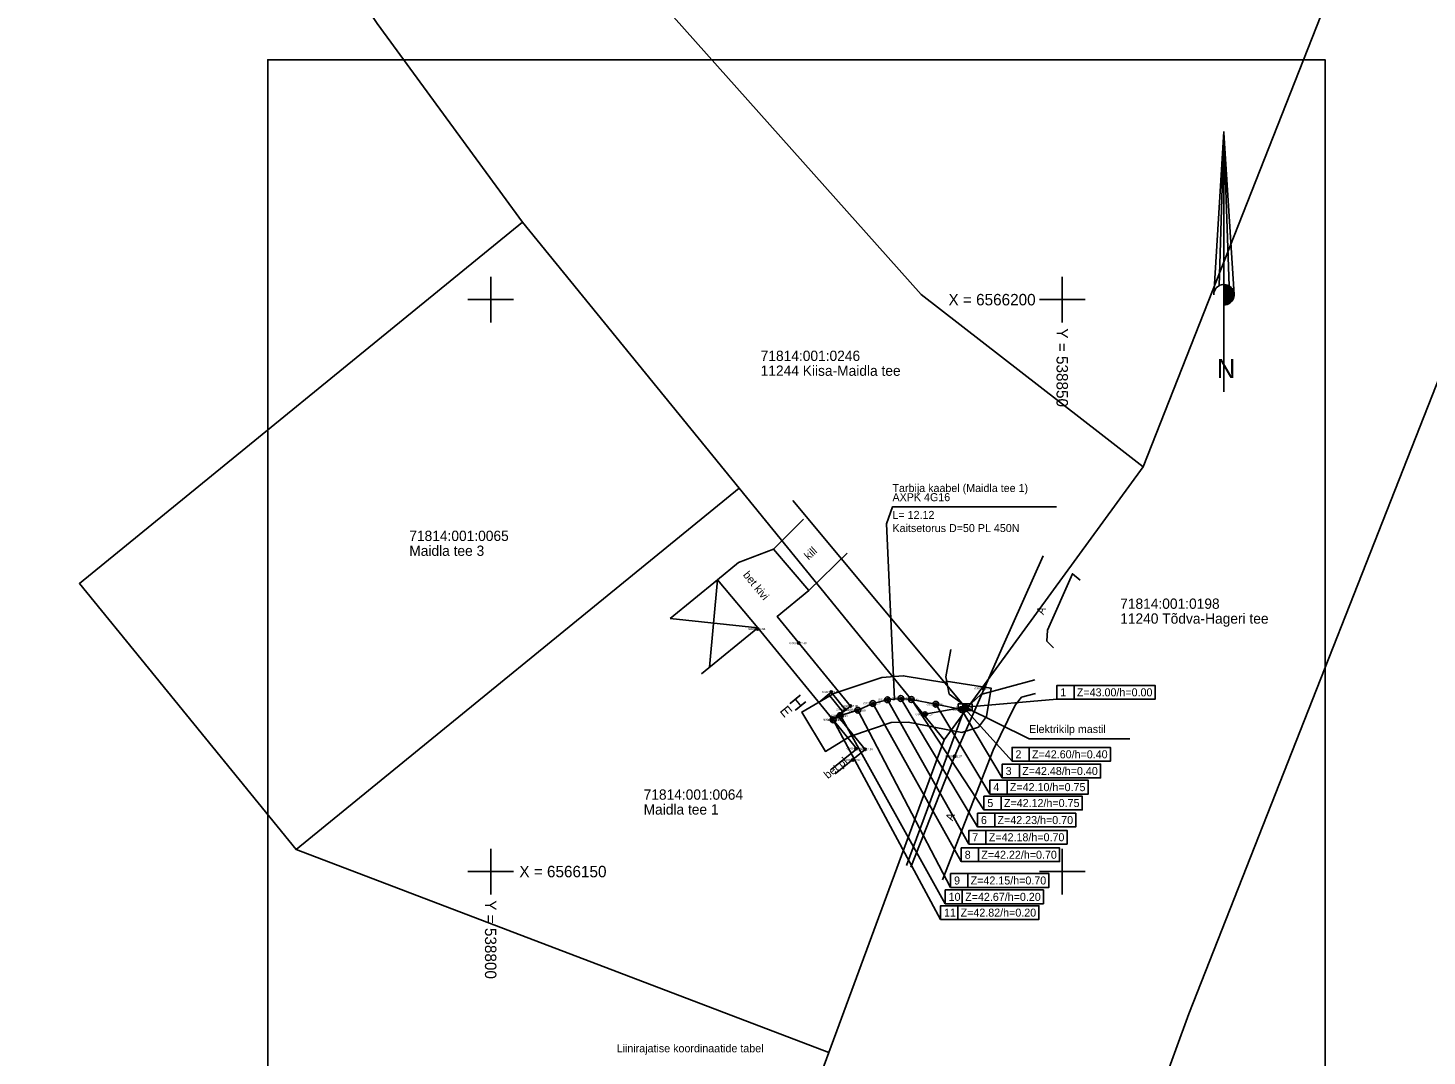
# Model space of a CAD drawing. Extents: x 537202 to 539193, y 6564585 to 6568304.
# Drawn here: x 538759.5 to 538881.9, y 6566133.9 to 6566223.7 of the extents above; entities that cross this region are included whole.
import ezdxf

# ---------------------------------------------------------------- set-up
doc = ezdxf.new("R2010")
doc.units = 0
for name, color, linetype in [('ABIJOONIS', 7, 'Continuous'), ('ELRAJATISMP', 7, 'Continuous'), ('HOONE', 7, 'Continuous'), ('HOONEDET', 7, 'Continuous'), ('KOORDPUNKT', 7, 'Continuous'), ('MOOTKORG-EH2000', 7, 'Continuous'), ('MOOTMPUNKT', 7, 'Continuous'), ('MOOTNR', 7, 'Continuous'), ('MOOTPIIR', 7, 'Continuous'), ('MPKAABEL', 7, 'Continuous'), ('MPOHULIIN', 7, 'Continuous'), ('PIIR', 7, 'Continuous'), ('POST', 7, 'Continuous'), ('TEE', 7, 'Continuous'), ('VORK', 7, 'Continuous'), ('VORMISTUS', 7, 'Continuous')]:
    doc.layers.add(name, color=color, linetype=linetype)

msp = doc.modelspace()

# ---------------------------------------------------------------- linework, layer by layer
at = {"layer": 'ABIJOONIS'}
for p, q in [((538851.03, 6566165.07), (538851.03, 6566166.27)), ((538847.11, 6566159.65), (538847.11, 6566160.85)), ((538846.25, 6566158.19), (538846.25, 6566159.39)), ((538845.17, 6566156.78), (538845.17, 6566157.98)), ((538844.65, 6566155.39), (538844.65, 6566156.59)), ((538844.09, 6566153.9), (538844.09, 6566155.1)), ((538843.33, 6566152.4), (538843.33, 6566153.6)), ((538842.67, 6566150.87), (538842.67, 6566152.07)), ((538841.74, 6566148.62), (538841.74, 6566149.82)), ((538841.26, 6566147.19), (538841.26, 6566148.39)), ((538840.86, 6566145.81), (538840.86, 6566147.01))]:
    msp.add_line(p, q, dxfattribs=at)
for points in [[(538841.51, 6566164.36), (538849.53, 6566165.07), (538858.13, 6566165.07), (538858.13, 6566166.27), (538849.53, 6566166.27), (538849.53, 6566165.07)], [(538833.43, 6566164.69), (538841.17, 6566150.87), (538849.77, 6566150.87), (538849.77, 6566152.07), (538841.17, 6566152.07), (538841.17, 6566150.87)], [(538834.71, 6566165.02), (538841.83, 6566152.4), (538850.43, 6566152.4), (538850.43, 6566153.6), (538841.83, 6566153.6), (538841.83, 6566152.4)], [(538835.89, 6566165.13), (538842.59, 6566153.9), (538851.19, 6566153.9), (538851.19, 6566155.1), (538842.59, 6566155.1), (538842.59, 6566153.9)], [(538836.8, 6566165.04), (538843.15, 6566155.39), (538851.75, 6566155.39), (538851.75, 6566156.59), (538843.15, 6566156.59), (538843.15, 6566155.39)], [(538838.95, 6566164.63), (538843.67, 6566156.78), (538852.27, 6566156.78), (538852.27, 6566157.98), (538843.67, 6566157.98), (538843.67, 6566156.78)], [(538830.59, 6566163.64), (538839.76, 6566147.19), (538848.36, 6566147.19), (538848.36, 6566148.39), (538839.76, 6566148.39), (538839.76, 6566147.19)], [(538832.12, 6566164.1), (538840.24, 6566148.62), (538848.84, 6566148.62), (538848.84, 6566149.82), (538840.24, 6566149.82), (538840.24, 6566148.62)], [(538841.2, 6566164.16), (538844.75, 6566158.19), (538853.35, 6566158.19), (538853.35, 6566159.39), (538844.75, 6566159.39), (538844.75, 6566158.19)], [(538841.49, 6566164.23), (538845.61, 6566159.65), (538854.21, 6566159.65), (538854.21, 6566160.85), (538845.61, 6566160.85), (538845.61, 6566159.65)], [(538829.96, 6566163.26), (538839.36, 6566145.81), (538847.96, 6566145.81), (538847.96, 6566147.01), (538839.36, 6566147.01), (538839.36, 6566145.81)]]:
    msp.add_lwpolyline(points, dxfattribs=at)
at = {"layer": 'ELRAJATISMP'}
for p, q in [((538841.37, 6566164.66), (538841.37, 6566164.07)), ((538841.64, 6566164.66), (538841.64, 6566164.07))]:
    msp.add_line(p, q, dxfattribs=at)
msp.add_lwpolyline([(538840.91, 6566164.66), (538842.11, 6566164.66), (538842.11, 6566164.07), (538840.91, 6566164.07)], close=True, dxfattribs=at)
msp.add_lwpolyline([(538841.51, 6566164.36), (538847.1, 6566161.61), (538855.92, 6566161.61)], dxfattribs=at)
at = {"layer": 'HOONE'}
msp.add_line((538830.79, 6566163.98), (538829.56, 6566165.5), dxfattribs=at)
for points in [[(538815.69, 6566172.11), (538819.84, 6566175.49), (538823.38, 6566171.3)], [(538829.8, 6566158.93), (538832.03, 6566160.73), (538823.38, 6566171.3), (538818.45, 6566167.29)], [(538828.7, 6566164.79), (538829.79, 6566165.69), (538831.02, 6566164.17), (538829.94, 6566163.28)]]:
    msp.add_lwpolyline(points, dxfattribs=at)
at = {"layer": 'HOONEDET'}
for p, q in [((538819.84, 6566175.49), (538819.15, 6566167.86)), ((538823.38, 6566171.3), (538815.69, 6566172.11)), ((538830.38, 6566163.59), (538832.76, 6566160.68))]:
    msp.add_line(p, q, dxfattribs=at)
at = {"layer": 'KOORDPUNKT'}
for centre, radius in [((538833.43, 6566164.69), 0.25), ((538833.43, 6566164.69), 0.0221), ((538833.43, 6566164.69), 0.025), ((538833.43, 6566164.69), 0.0132), ((538833.43, 6566164.69), 0.0161), ((538833.43, 6566164.69), 0.0191), ((538833.43, 6566164.69), 0.0043), ((538833.43, 6566164.69), 0.00726), ((538833.43, 6566164.69), 0.0102), ((538834.71, 6566165.02), 0.25), ((538834.71, 6566165.02), 0.025), ((538834.71, 6566165.02), 0.0221), ((538834.71, 6566165.02), 0.0161), ((538834.71, 6566165.02), 0.0191), ((538834.71, 6566165.02), 0.0102), ((538834.71, 6566165.02), 0.0132), ((538834.71, 6566165.02), 0.0043), ((538834.71, 6566165.02), 0.00726), ((538835.89, 6566165.13), 0.25), ((538835.89, 6566165.13), 0.025), ((538835.89, 6566165.13), 0.0221), ((538835.89, 6566165.13), 0.0132), ((538835.89, 6566165.13), 0.0161), ((538835.89, 6566165.13), 0.0191), ((538835.89, 6566165.13), 0.0043), ((538835.89, 6566165.13), 0.00726), ((538835.89, 6566165.13), 0.0102), ((538836.8, 6566165.04), 0.25), ((538836.8, 6566165.04), 0.0221), ((538836.8, 6566165.04), 0.025), ((538836.8, 6566165.04), 0.0161), ((538836.8, 6566165.04), 0.0191), ((538836.8, 6566165.04), 0.0132), ((538836.8, 6566165.04), 0.00726), ((538836.8, 6566165.04), 0.0102), ((538836.8, 6566165.04), 0.0043), ((538838.95, 6566164.63), 0.25), ((538838.95, 6566164.63), 0.025), ((538838.95, 6566164.63), 0.0221), ((538838.95, 6566164.63), 0.0161), ((538838.95, 6566164.63), 0.0191), ((538838.95, 6566164.63), 0.0102), ((538838.95, 6566164.63), 0.0132), ((538838.95, 6566164.63), 0.0043), ((538838.95, 6566164.63), 0.00726), ((538829.96, 6566163.26), 0.25), ((538830.59, 6566163.64), 0.25), ((538830.59, 6566163.64), 0.0191), ((538830.59, 6566163.64), 0.0221), ((538830.59, 6566163.64), 0.025), ((538830.59, 6566163.64), 0.0161), ((538830.59, 6566163.64), 0.0102), ((538830.59, 6566163.64), 0.0132), ((538830.59, 6566163.64), 0.00726), ((538830.59, 6566163.64), 0.0043), ((538832.12, 6566164.1), 0.25), ((538832.12, 6566164.1), 0.0221), ((538832.12, 6566164.1), 0.025), ((538832.12, 6566164.1), 0.0191), ((538832.12, 6566164.1), 0.0132), ((538832.12, 6566164.1), 0.0161), ((538832.12, 6566164.1), 0.0102), ((538832.12, 6566164.1), 0.0043), ((538832.12, 6566164.1), 0.00726), ((538841.2, 6566164.16), 0.25), ((538841.2, 6566164.16), 0.025), ((538841.2, 6566164.16), 0.0191), ((538841.2, 6566164.16), 0.0221), ((538841.2, 6566164.16), 0.0132), ((538841.2, 6566164.16), 0.0161), ((538841.2, 6566164.16), 0.0102), ((538841.2, 6566164.16), 0.0043), ((538841.2, 6566164.16), 0.00726), ((538841.49, 6566164.23), 0.25), ((538841.51, 6566164.36), 0.188), ((538841.49, 6566164.23), 0.025), ((538841.49, 6566164.23), 0.0221), ((538841.49, 6566164.23), 0.0161), ((538841.49, 6566164.23), 0.0191), ((538841.49, 6566164.23), 0.0102), ((538841.49, 6566164.23), 0.0132), ((538841.51, 6566164.36), 0.0143), ((538841.51, 6566164.36), 0.0165), ((538841.51, 6566164.36), 0.0188), ((538841.49, 6566164.23), 0.0043), ((538841.49, 6566164.23), 0.00726), ((538841.51, 6566164.36), 0.0121), ((538841.51, 6566164.36), 0.00323), ((538841.51, 6566164.36), 0.00545), ((538841.51, 6566164.36), 0.00766), ((538841.51, 6566164.36), 0.00988), ((538829.96, 6566163.26), 0.0221), ((538829.96, 6566163.26), 0.025), ((538829.96, 6566163.26), 0.0191), ((538829.96, 6566163.26), 0.0102), ((538829.96, 6566163.26), 0.0132), ((538829.96, 6566163.26), 0.0161), ((538829.96, 6566163.26), 0.0043), ((538829.96, 6566163.26), 0.00726)]:
    msp.add_circle(centre, radius, dxfattribs=at)
at = {"layer": 'MOOTMPUNKT'}
for centre in [(538823.35, 6566171.2), (538826.95, 6566169.97), (538843.12, 6566166), (538829.79, 6566165.69), (538833.43, 6566164.69), (538834.71, 6566165.02), (538835.89, 6566165.13), (538836.8, 6566165.04), (538838.95, 6566164.63), (538830.38, 6566163.59), (538830.59, 6566163.64), (538831.02, 6566164.17), (538831.47, 6566164.47), (538832.12, 6566164.1), (538837.99, 6566163.75), (538841.2, 6566164.16), (538841.49, 6566164.23), (538841.51, 6566164.36), (538829.89, 6566163.27), (538829.96, 6566163.26), (538831.67, 6566159.76), (538831.95, 6566160.75), (538832.76, 6566160.68), (538840.58, 6566160.07)]:
    msp.add_circle(centre, 0.1, dxfattribs=at)
at = {"layer": 'MOOTPIIR'}
msp.add_lwpolyline([(538839.81, 6566166.49), (538839.84, 6566166.64), (538843.79, 6566166.03), (538843.37, 6566163.55), (538842.67, 6566162.61), (538841.23, 6566162.16), (538836.51, 6566163.06), (538835.05, 6566163.04), (538831.41, 6566161.8), (538829.28, 6566160.51), (538827.21, 6566163.94), (538830.01, 6566165.56), (538834.21, 6566166.96), (538836.09, 6566167.12)], close=True, dxfattribs=at)
at = {"layer": 'MPKAABEL'}
for points in [[(538835.34, 6566165.08), (538834.63, 6566180.4), (538835.15, 6566181.88), (538849.51, 6566181.88)], [(538841.6, 6566164.27), (538841.16, 6566164.74), (538840.1, 6566165.52), (538839.83, 6566167.02), (538840.26, 6566169.42)], [(538841.6, 6566164.27), (538842.87, 6566165.49), (538847.61, 6566166.75)], [(538841.51, 6566164.36), (538841.49, 6566164.23), (538841.2, 6566164.16), (538838.95, 6566164.63), (538836.8, 6566165.04), (538835.89, 6566165.13), (538834.71, 6566165.02), (538833.43, 6566164.69), (538832.12, 6566164.1), (538830.59, 6566163.64), (538829.96, 6566163.26)], [(538841.49, 6566164.23), (538841.2, 6566164.16), (538838.95, 6566164.63), (538836.8, 6566165.04), (538835.89, 6566165.13), (538834.71, 6566165.02), (538833.43, 6566164.69), (538832.12, 6566164.1), (538830.59, 6566163.64), (538829.96, 6566163.26)]]:
    msp.add_lwpolyline(points, dxfattribs=at)
at = {"layer": 'MPOHULIIN'}
msp.add_lwpolyline([(538826.42, 6566182.43), (538841.51, 6566164.36), (538836.38, 6566150.53)], dxfattribs=at)
at = {"layer": 'PIIR'}
for points in [[(538894.8, 6566812.41), (538963.18, 6566613.93), (538982.42, 6566557.85), (538985.96, 6566511.92), (538967.86, 6566486.92), (538925.14, 6566394.61), (538935.87, 6566385.3), (538927.65, 6566364.44), (538857.08, 6566185.39), (538839.66, 6566161.53), (538829.57, 6566134.19), (538819.13, 6566105.9), (538808.44, 6566077.86), (538798.42, 6566051.03)], [(538807.08, 6565989.5), (538861.09, 6566137.56), (538946.91, 6566355.55), (538963.03, 6566381.4), (538980.53, 6566430.76), (538997.55, 6566478.76), (539004.3, 6566477.92), (539003.88, 6566538.51), (539001.49, 6566552.38), (538994.83, 6566581.91), (538987.69, 6566605.33), (538973.55, 6566645.42)], [(538546.04, 6566419.35), (538611.98, 6566353.64), (538643.18, 6566325.97), (538667.74, 6566309.58), (538680.15, 6566297.65), (538694.98, 6566288.02), (538732.42, 6566269.19), (538757.68, 6566256.49), (538769.54, 6566249.34), (538784.19, 6566232.93), (538790.08, 6566224.15), (538802.78, 6566206.77), (538821.74, 6566183.52), (538839.66, 6566161.53), (538857.08, 6566185.39), (538853.41, 6566188.24), (538837.66, 6566200.46), (538815.02, 6566225.8), (538793.5, 6566255.4), (538773.23, 6566271.88), (538696.61, 6566311.53), (538682.79, 6566326.11), (538659.23, 6566343.44), (538633.21, 6566367.65)]]:
    msp.add_lwpolyline(points, dxfattribs=at)
for points in [[(538821.74, 6566183.52), (538802.78, 6566206.77), (538764.03, 6566175.18), (538770.06, 6566167.78), (538782.98, 6566151.93)], [(538839.66, 6566161.53), (538821.74, 6566183.52), (538782.98, 6566151.93), (538829.57, 6566134.19)]]:
    msp.add_lwpolyline(points, close=True, dxfattribs=at)
at = {"layer": 'POST'}
msp.add_lwpolyline([(538837.99, 6566163.75), (538841.42, 6566164.38)], dxfattribs=at)
for centre, radius in [((538841.51, 6566164.36), 0.25), ((538837.99, 6566163.75), 0.2), ((538841.51, 6566164.36), 0.0234)]:
    msp.add_circle(centre, radius, dxfattribs=at)
at = {"layer": 'TEE'}
for p, q in [((538824.75, 6566178.19), (538827.37, 6566180.8)), ((538827.82, 6566174.58), (538831.2, 6566177.83))]:
    msp.add_line(p, q, dxfattribs=at)
for points in [[(538830.38, 6566163.59), (538831.47, 6566164.47), (538825.06, 6566172.29), (538827.82, 6566174.58), (538824.75, 6566178.19), (538821.69, 6566177.01), (538819.84, 6566175.49)], [(538848.34, 6566177.59), (538844.84, 6566169.75), (538840.58, 6566160.07), (538836.77, 6566150.38)], [(538849.23, 6566169.57), (538848.66, 6566170.14), (538848.71, 6566171.11), (538850.89, 6566176.04), (538851.58, 6566175.48)], [(538847.65, 6566165.58), (538846.45, 6566165.25), (538845.89, 6566164.54), (538843.97, 6566160.62), (538839.54, 6566149.29)], [(538830.13, 6566158.53), (538832.76, 6566160.66), (538830.38, 6566163.59)]]:
    msp.add_lwpolyline(points, dxfattribs=at)
at = {"layer": 'VORK'}
for p, q in [((538800, 6566202), (538800, 6566198)), ((538850, 6566202), (538850, 6566198)), ((538798, 6566200), (538802, 6566200)), ((538848, 6566200), (538852, 6566200)), ((538800, 6566152), (538800, 6566148)), ((538850, 6566152), (538850, 6566148)), ((538798, 6566150), (538802, 6566150)), ((538848, 6566150), (538852, 6566150))]:
    msp.add_line(p, q, dxfattribs=at)
at = {"layer": 'VORMISTUS'}
msp.add_lwpolyline([(538780.5, 6566077.47), (538780.5, 6566220.97), (538873, 6566220.97), (538873, 6566077.47)], close=True, dxfattribs=at)
for points in [[(538864.15, 6566214.69), (538863.25, 6566200.43)], [(538864.15, 6566214.59), (538863.73, 6566201.22)], [(538864.14, 6566214.64), (538864.61, 6566201.19)], [(538864.15, 6566214.69), (538864.15, 6566191.94)], [(538864.15, 6566214.58), (538865.04, 6566200.45)], [(538864.15, 6566201.32), (538864.19, 6566201.32)], [(538864.15, 6566201.32), (538864.17, 6566201.32)], [(538864.15, 6566201.22), (538864.58, 6566201.22)], [(538864.15, 6566201.11), (538864.72, 6566201.11)], [(538864.15, 6566201.01), (538864.81, 6566201.01)], [(538864.15, 6566200.91), (538864.89, 6566200.91)], [(538864.15, 6566200.8), (538864.95, 6566200.8)], [(538864.15, 6566200.7), (538864.99, 6566200.7)], [(538864.15, 6566200.6), (538865.02, 6566200.6)], [(538864.15, 6566200.49), (538865.03, 6566200.49)], [(538864.15, 6566200.39), (538865.04, 6566200.39)], [(538864.15, 6566200.29), (538865.02, 6566200.29)], [(538864.15, 6566200.19), (538865, 6566200.19)], [(538864.22, 6566199.55), (538864.22, 6566201.31)], [(538864.32, 6566199.57), (538864.32, 6566201.3)], [(538864.43, 6566199.58), (538864.43, 6566201.27)], [(538864.53, 6566199.63), (538864.53, 6566201.23)], [(538864.63, 6566199.69), (538864.63, 6566201.19)], [(538864.73, 6566199.77), (538864.73, 6566201.1)], [(538864.84, 6566199.87), (538864.84, 6566200.98)], [(538864.94, 6566200.04), (538864.94, 6566200.84)], [(538864.14, 6566199.57), (538864.34, 6566199.57)], [(538864.15, 6566200.08), (538864.96, 6566200.08)], [(538864.15, 6566199.98), (538864.91, 6566199.98)], [(538864.15, 6566199.88), (538864.84, 6566199.88)], [(538864.15, 6566199.77), (538864.74, 6566199.77)], [(538864.15, 6566199.67), (538864.6, 6566199.67)]]:
    msp.add_lwpolyline(points, dxfattribs=at)
msp.add_arc((538864.15, 6566200.43), 0.894, 270.3348, 180.6244, dxfattribs=at)

# ---------------------------------------------------------------- texts
at = {"layer": 'ABIJOONIS'}
for s, p in [('1', (538849.83, 6566165.32)), ('Z=43.00/h=0.00', (538851.28, 6566165.32)), ('2', (538845.91, 6566159.9)), ('Z=42.60/h=0.40', (538847.36, 6566159.9)), ('3', (538845.05, 6566158.44)), ('Z=42.48/h=0.40', (538846.5, 6566158.44)), ('4', (538843.97, 6566157.03)), ('Z=42.10/h=0.75', (538845.42, 6566157.03)), ('5', (538843.45, 6566155.64)), ('Z=42.12/h=0.75', (538844.9, 6566155.64)), ('6', (538842.89, 6566154.15)), ('Z=42.23/h=0.70', (538844.34, 6566154.15)), ('7', (538842.13, 6566152.65)), ('Z=42.18/h=0.70', (538843.58, 6566152.65)), ('8', (538841.47, 6566151.12)), ('Z=42.22/h=0.70', (538842.92, 6566151.12)), ('9', (538840.54, 6566148.87)), ('Z=42.15/h=0.70', (538841.99, 6566148.87)), ('10', (538840.06, 6566147.44)), ('Z=42.67/h=0.20', (538841.51, 6566147.44)), ('11', (538839.66, 6566146.06)), ('Z=42.82/h=0.20', (538841.11, 6566146.06)), ('Liinirajatise koordinaatide tabel', (538811.02, 6566134.2))]:
    msp.add_text(s, height=0.7, dxfattribs=at).set_placement(p)
at = {"layer": 'ELRAJATISMP'}
msp.add_text('Elektrikilp mastil', height=0.7, dxfattribs=at).set_placement((538847.1, 6566162.11))
at = {"layer": 'HOONE'}
for s, height, p in [('H', 1.2, (538826.04, 6566164.83)), ('E', 0.9, (538825.24, 6566164.03))]:
    msp.add_text(s, height=height, rotation=309.4046, dxfattribs=at).set_placement(p)
at = {"layer": 'HOONEDET'}
for s, rotation, p in [('bet kivi', 309.2334, (538822.03, 6566175.91)), ('bet pl', 39.3794, (538829.5, 6566158.07))]:
    msp.add_text(s, height=0.7, rotation=rotation, dxfattribs=at).set_placement(p)
at = {"layer": 'MOOTKORG-EH2000'}
for s, p in [(' 42.94', (538823.35, 6566171.12)), (' 42.83', (538826.95, 6566169.88)), (' 42.97', (538843.12, 6566165.92)), (' 42.95', (538829.79, 6566165.6)), (' 42.92', (538833.43, 6566164.61)), (' 42.88', (538834.71, 6566164.93)), (' 42.93', (538835.89, 6566165.05)), (' 42.87', (538836.8, 6566164.95)), (' 42.85', (538838.95, 6566164.54)), (' 42.90', (538830.38, 6566163.5)), (' 42.87', (538830.59, 6566163.55)), (' 42.93', (538831.02, 6566164.08)), (' 42.88', (538831.47, 6566164.38)), (' 42.85', (538832.12, 6566164.01)), (' 43.19', (538837.99, 6566163.67)), (' 42.88', (538841.2, 6566164.07)), (' 43.00', (538841.49, 6566164.14)), (' 43.00', (538841.51, 6566164.28)), (' 43.00', (538829.89, 6566163.18)), (' 43.02', (538829.96, 6566163.17)), (' 42.97', (538831.67, 6566159.67)), (' 42.96', (538831.95, 6566160.67)), (' 42.89', (538832.76, 6566160.59)), (' 42.97', (538840.58, 6566159.99))]:
    msp.add_text(s, height=0.175, dxfattribs=at).set_placement(p)
at = {"layer": 'MOOTNR'}
for s, p in [('GS0017 ', (538822.54, 6566171.12)), ('GS0018 ', (538826.14, 6566169.88)), ('GS0025 ', (538842.3, 6566165.92)), ('GS0016 ', (538828.97, 6566165.6)), ('GS0010 ', (538832.61, 6566164.61)), ('GS0009 ', (538833.89, 6566164.93)), ('GS0008 ', (538835.07, 6566165.05)), ('GS0007 ', (538835.98, 6566164.95)), ('GS0006 ', (538838.14, 6566164.54)), ('GS0020 ', (538829.57, 6566163.5)), ('GS0012 ', (538829.77, 6566163.55)), ('GS0015 ', (538830.21, 6566164.08)), ('GS0019 ', (538830.66, 6566164.38)), ('GS0011 ', (538831.3, 6566164.01)), ('GS0005 ', (538837.17, 6566163.67)), ('GS0004 ', (538840.38, 6566164.07)), ('GS0003 ', (538840.68, 6566164.14)), ('GS0002 ', (538840.69, 6566164.28)), ('GS0014 ', (538829.07, 6566163.18)), ('GS0013 ', (538829.15, 6566163.17)), ('GS0023 ', (538830.85, 6566159.67)), ('GS0021 ', (538831.14, 6566160.67)), ('GS0022 ', (538831.94, 6566160.59)), ('GS0024 ', (538839.77, 6566159.99))]:
    msp.add_text(s, height=0.175, dxfattribs=at).set_placement(p)
at = {"layer": 'MPKAABEL'}
for s, p in [('AXPK 4G16', (538835.15, 6566182.38)), ('Tarbija kaabel (Maidla tee 1)', (538835.15, 6566183.18)), ('L= 12.12', (538835.15, 6566180.83)), ('Kaitsetorus D=50 PL 450N', (538835.15, 6566179.68))]:
    msp.add_text(s, height=0.7, dxfattribs=at).set_placement(p)
at = {"layer": 'PIIR'}
for s, p in [('71814:001:0246', (538823.62, 6566194.64)), ('11244 Kiisa-Maidla tee', (538823.62, 6566193.34)), ('71814:001:0065', (538792.88, 6566178.9)), ('Maidla tee 3', (538792.88, 6566177.6)), ('71814:001:0198', (538855.07, 6566172.97)), ('11240 Tõdva-Hageri tee', (538855.07, 6566171.67)), ('71814:001:0064', (538813.38, 6566156.28)), ('Maidla tee 1', (538813.38, 6566154.98))]:
    msp.add_text(s, height=0.9, dxfattribs=at).set_placement(p)
at = {"layer": 'TEE'}
for s, rotation, p in [('kill', 41.9606, (538827.81, 6566177.2)), ('A', 69.206, (538848.36, 6566172.41)), ('A', 69.206, (538840.41, 6566154.38))]:
    msp.add_text(s, height=0.7, rotation=rotation, dxfattribs=at).set_placement(p)
at = {"layer": 'VORK'}
for s, p in [('X = 6566200', (538840.05, 6566199.5)), ('X = 6566150', (538802.51, 6566149.5))]:
    msp.add_text(s, height=1, dxfattribs=at).set_placement(p)
for s, p in [('Y = 538850', (538849.5, 6566197.49)), ('Y = 538800', (538799.5, 6566147.49))]:
    msp.add_text(s, height=1, rotation=270, dxfattribs=at).set_placement(p)
at = {"layer": 'VORMISTUS'}
msp.add_text('N', height=1.67, dxfattribs=at).set_placement((538863.53, 6566193.14))

doc.saveas('drawing.dxf')
